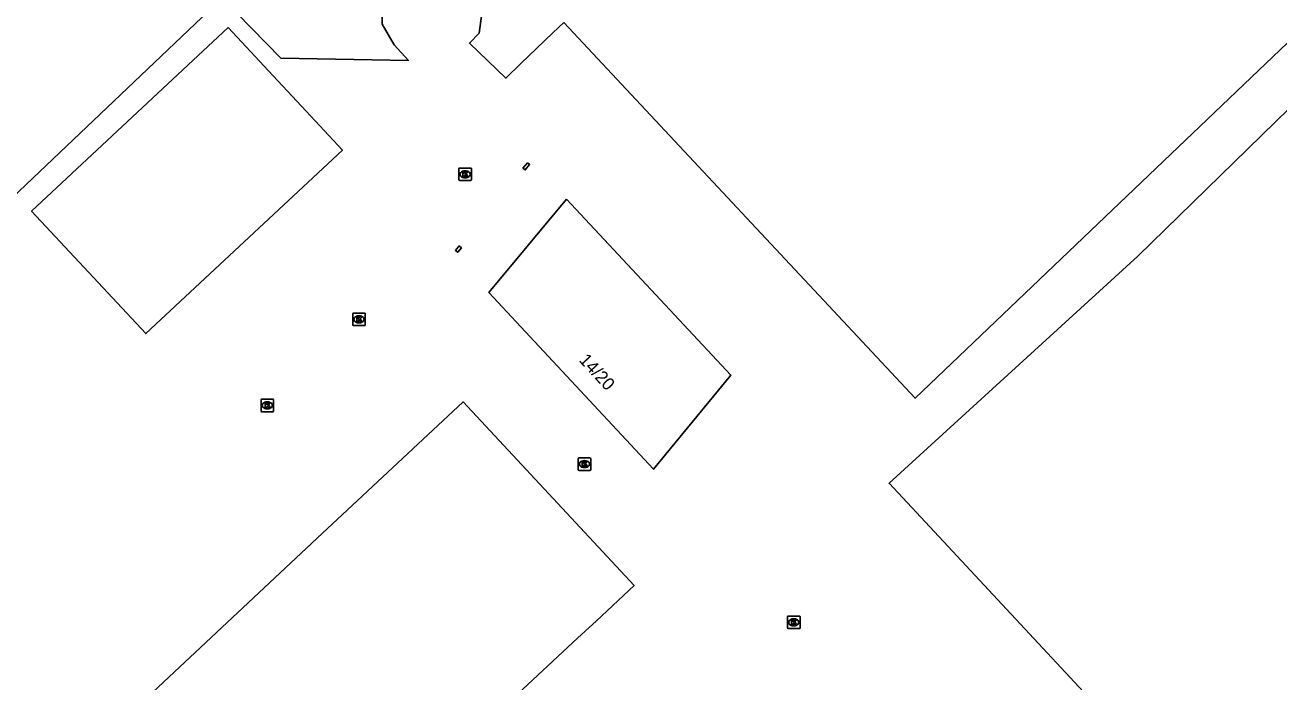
# Model space of a CAD drawing. Extents: x 157154 to 159278, y 385000 to 386650.
# Drawn here: x 157736 to 157835.7, y 386063.9 to 386116.2 of the extents above; entities that cross this region are included whole.
import ezdxf

# ---------------------------------------------------------------- set-up
doc = ezdxf.new("R2010")
doc.units = 0
for name, color, linetype in [('IMGEO_Bouwland', 7, 'Continuous'), ('IMGEO_Grasland_agrarisch', 7, 'Continuous'), ('IMGEO_Kolk', 7, 'Continuous'), ('IMGEO_Pand', 7, 'Continuous'), ('IMGEO_Pand_nummerreeks', 7, 'Continuous')]:
    doc.layers.add(name, color=color, linetype=linetype)

msp = doc.modelspace()

# ---------------------------------------------------------------- linework, layer by layer
at = {"layer": 'IMGEO_Bouwland'}
for points in [[(157842.48, 386039.201), (157804.71, 386079.734), (157824.5, 386097.811), (157874.848, 386146.922), (157921.221, 386191.276), (157933.341, 386204.005)], [(157778.816, 386116.384), (157777.946, 386115.555), (157775.389, 386113.118), (157774.218, 386111.946), (157771.308, 386114.755), (157772.081, 386115.542), (157772.382, 386117.691), (157772.313, 386119.081), (157771.652, 386120.262), (157770.123, 386121.096), (157768.455, 386121.548), (157766.613, 386121.201), (157765.327, 386120.332), (157764.319, 386118.559), (157764.354, 386116.266), (157765.327, 386114.598), (157766.451, 386113.359), (157756.298, 386113.561), (157751.643, 386118.342), (157707.976, 386076.857), (157706.46, 386078.626), (157702.502, 386080.31), (157698.544, 386079.468), (157675.973, 386060.014)]]:
    msp.add_lwpolyline(points, dxfattribs=at)
at = {"layer": 'IMGEO_Grasland_agrarisch'}
msp.add_lwpolyline([(157931.712, 386205.711), (157806.769, 386086.503), (157778.816, 386116.384)], dxfattribs=at)
at = {"layer": 'IMGEO_Kolk'}
for p, q in [((157770.467, 386103.886), (157770.467, 386104.738)), ((157770.542, 386104.812), (157771.394, 386104.812)), ((157770.978, 386104.032), (157770.953, 386104.032)), ((157770.955, 386104.592), (157770.98, 386104.592)), ((157771.468, 386104.738), (157771.468, 386103.886)), ((157771.394, 386103.812), (157770.542, 386103.812)), ((157762.024, 386092.35), (157762.024, 386093.202)), ((157762.099, 386093.276), (157762.951, 386093.276)), ((157762.512, 386093.056), (157762.537, 386093.056)), ((157763.025, 386093.202), (157763.025, 386092.35)), ((157762.951, 386092.276), (157762.099, 386092.276)), ((157762.535, 386092.496), (157762.51, 386092.496)), ((157754.727, 386085.506), (157754.727, 386086.358)), ((157754.802, 386086.432), (157755.654, 386086.432)), ((157755.215, 386086.212), (157755.24, 386086.212)), ((157755.728, 386086.358), (157755.728, 386085.506)), ((157755.654, 386085.432), (157754.802, 386085.432)), ((157755.238, 386085.652), (157755.213, 386085.652)), ((157779.965, 386080.838), (157779.965, 386081.69)), ((157780.04, 386081.764), (157780.892, 386081.764)), ((157780.453, 386081.544), (157780.478, 386081.544)), ((157780.966, 386081.69), (157780.966, 386080.838)), ((157780.892, 386080.764), (157780.04, 386080.764)), ((157780.476, 386080.984), (157780.451, 386080.984)), ((157796.615, 386068.249), (157796.615, 386069.101)), ((157796.69, 386069.175), (157797.542, 386069.175)), ((157797.616, 386069.101), (157797.616, 386068.249)), ((157797.542, 386068.175), (157796.69, 386068.175)), ((157797.126, 386068.395), (157797.101, 386068.395)), ((157797.103, 386068.955), (157797.128, 386068.955))]:
    msp.add_line(p, q, dxfattribs=at)
for points in [[(157770.467, 386103.886), (157770.467, 386104.738)], [(157770.542, 386104.812), (157771.394, 386104.812)], [(157770.788, 386104.512), (157770.911, 386104.512), (157770.911, 386104.361), (157771.041, 386104.512), (157771.205, 386104.512), (157771.059, 386104.361), (157771.212, 386104.112), (157771.06, 386104.112), (157770.975, 386104.276), (157770.911, 386104.209), (157770.911, 386104.112), (157770.788, 386104.112), (157770.788, 386104.512)], [(157771.468, 386104.738), (157771.468, 386103.886)], [(157771.394, 386103.812), (157770.542, 386103.812)], [(157762.024, 386092.35), (157762.024, 386093.202)], [(157762.099, 386093.276), (157762.951, 386093.276)], [(157763.025, 386093.202), (157763.025, 386092.35)], [(157762.951, 386092.276), (157762.099, 386092.276)], [(157762.345, 386092.976), (157762.468, 386092.976), (157762.468, 386092.825), (157762.598, 386092.976), (157762.762, 386092.976), (157762.616, 386092.825), (157762.769, 386092.576), (157762.617, 386092.576), (157762.532, 386092.74), (157762.468, 386092.673), (157762.468, 386092.576), (157762.345, 386092.576), (157762.345, 386092.976)], [(157754.727, 386085.506), (157754.727, 386086.358)], [(157754.802, 386086.432), (157755.654, 386086.432)], [(157755.048, 386086.132), (157755.171, 386086.132), (157755.171, 386085.981), (157755.301, 386086.132), (157755.465, 386086.132), (157755.319, 386085.981), (157755.472, 386085.732), (157755.32, 386085.732), (157755.235, 386085.896), (157755.171, 386085.829), (157755.171, 386085.732), (157755.048, 386085.732), (157755.048, 386086.132)], [(157755.728, 386086.358), (157755.728, 386085.506)], [(157755.654, 386085.432), (157754.802, 386085.432)], [(157779.965, 386080.838), (157779.965, 386081.69)], [(157780.04, 386081.764), (157780.892, 386081.764)], [(157780.286, 386081.464), (157780.409, 386081.464), (157780.409, 386081.313), (157780.539, 386081.464), (157780.703, 386081.464), (157780.557, 386081.313), (157780.71, 386081.064), (157780.558, 386081.064), (157780.473, 386081.228), (157780.409, 386081.161), (157780.409, 386081.064), (157780.286, 386081.064), (157780.286, 386081.464)], [(157780.966, 386081.69), (157780.966, 386080.838)], [(157780.892, 386080.764), (157780.04, 386080.764)], [(157796.615, 386068.249), (157796.615, 386069.101)], [(157796.69, 386069.175), (157797.542, 386069.175)], [(157797.616, 386069.101), (157797.616, 386068.249)], [(157797.542, 386068.175), (157796.69, 386068.175)], [(157796.936, 386068.875), (157797.059, 386068.875), (157797.059, 386068.724), (157797.189, 386068.875), (157797.353, 386068.875), (157797.207, 386068.724), (157797.36, 386068.475), (157797.208, 386068.475), (157797.123, 386068.639), (157797.059, 386068.572), (157797.059, 386068.475), (157796.936, 386068.475), (157796.936, 386068.875)]]:
    msp.add_lwpolyline(points, dxfattribs=at)
for centre, start, end in [((157770.544, 386104.736), 91.55205, 178.44795), ((157770.544, 386104.736), 91.55205, 178.44795), ((157771.392, 386104.736), 1.55205, 88.44795), ((157771.392, 386104.736), 1.55205, 88.44795), ((157770.544, 386103.888), 181.55205, 268.44795), ((157770.544, 386103.888), 181.55205, 268.44795), ((157771.392, 386103.888), 271.55205, 358.44795), ((157771.392, 386103.888), 271.55205, 358.44795), ((157762.101, 386093.2), 91.55205, 178.44795), ((157762.101, 386093.2), 91.55205, 178.44795), ((157762.949, 386093.2), 1.55205, 88.44795), ((157762.949, 386093.2), 1.55205, 88.44795), ((157762.101, 386092.352), 181.55205, 268.44795), ((157762.101, 386092.352), 181.55205, 268.44795), ((157762.949, 386092.352), 271.55205, 358.44795), ((157762.949, 386092.352), 271.55205, 358.44795), ((157754.804, 386086.356), 91.55205, 178.44795), ((157754.804, 386086.356), 91.55205, 178.44795), ((157755.652, 386086.356), 1.55205, 88.44795), ((157755.652, 386086.356), 1.55205, 88.44795), ((157754.804, 386085.508), 181.55205, 268.44795), ((157754.804, 386085.508), 181.55205, 268.44795), ((157755.652, 386085.508), 271.55205, 358.44795), ((157755.652, 386085.508), 271.55205, 358.44795), ((157780.042, 386081.688), 91.55205, 178.44795), ((157780.042, 386081.688), 91.55205, 178.44795), ((157780.89, 386081.688), 1.55205, 88.44795), ((157780.89, 386081.688), 1.55205, 88.44795), ((157780.042, 386080.84), 181.55205, 268.44795), ((157780.042, 386080.84), 181.55205, 268.44795), ((157780.89, 386080.84), 271.55205, 358.44795), ((157780.89, 386080.84), 271.55205, 358.44795), ((157796.692, 386069.099), 91.55205, 178.44795), ((157796.692, 386069.099), 91.55205, 178.44795), ((157797.54, 386069.099), 1.55205, 88.44795), ((157797.54, 386069.099), 1.55205, 88.44795), ((157796.692, 386068.251), 181.55205, 268.44795), ((157796.692, 386068.251), 181.55205, 268.44795), ((157797.54, 386068.251), 271.55205, 358.44795), ((157797.54, 386068.251), 271.55205, 358.44795)]:
    msp.add_arc(centre, 0.0765, start, end, dxfattribs=at)
for centre, major_axis, ratio, start_param, end_param in [((157770.954, 386104.312), (-0.387, 0.002), 0.722429, 4.712389, 7.853982), ((157770.979, 386104.312), (-0.39, 0.002), 0.717154, 1.570796, 4.712389), ((157762.511, 386092.776), (-0.387, 0.002), 0.722429, 4.712389, 7.853982), ((157762.536, 386092.776), (-0.39, 0.002), 0.717154, 1.570796, 4.712389), ((157755.214, 386085.932), (-0.387, 0.002), 0.722429, 4.712389, 7.853982), ((157755.239, 386085.932), (-0.39, 0.002), 0.717154, 1.570796, 4.712389), ((157780.452, 386081.264), (-0.387, 0.002), 0.722429, 4.712389, 7.853982), ((157780.477, 386081.264), (-0.39, 0.002), 0.717154, 1.570796, 4.712389), ((157797.102, 386068.675), (-0.387, 0.002), 0.722429, 4.712389, 7.853982), ((157797.127, 386068.675), (-0.39, 0.002), 0.717154, 1.570796, 4.712389)]:
    msp.add_ellipse(centre, major_axis=major_axis, ratio=ratio, start_param=start_param, end_param=end_param, dxfattribs=at)
at = {"layer": 'IMGEO_Pand'}
for points in [[(157752.118, 386115.978), (157755.333, 386112.533), (157757.958, 386109.719), (157761.204, 386106.24), (157745.558, 386091.642), (157736.473, 386101.379), (157752.118, 386115.978)], [(157775.925, 386105.236), (157776.102, 386105.09), (157775.749, 386104.66), (157775.572, 386104.806), (157775.925, 386105.236)], [(157779.045, 386102.324), (157792.111, 386088.328), (157785.956, 386080.851), (157772.865, 386094.901), (157779.045, 386102.324)], [(157770.483, 386098.616), (157770.668, 386098.463), (157770.379, 386098.114), (157770.19, 386098.262), (157770.483, 386098.616)], [(157741.775, 386042.334), (157733.426, 386051.268), (157759.205, 386075.362), (157770.805, 386086.203), (157784.411, 386071.596), (157781.414, 386068.804), (157779.913, 386067.407), (157769.183, 386057.413), (157767.599, 386059.119), (157765.18, 386056.821), (157761.501, 386060.77), (157753.047, 386052.869), (157742.12, 386042.657)]]:
    msp.add_lwpolyline(points, dxfattribs=at)

# ---------------------------------------------------------------- texts
at = {"layer": 'IMGEO_Pand_nummerreeks'}
msp.add_text('14/20', height=1, rotation=312.77682, dxfattribs=at).set_placement((157779.969, 386089.488))

doc.saveas('drawing.dxf')
